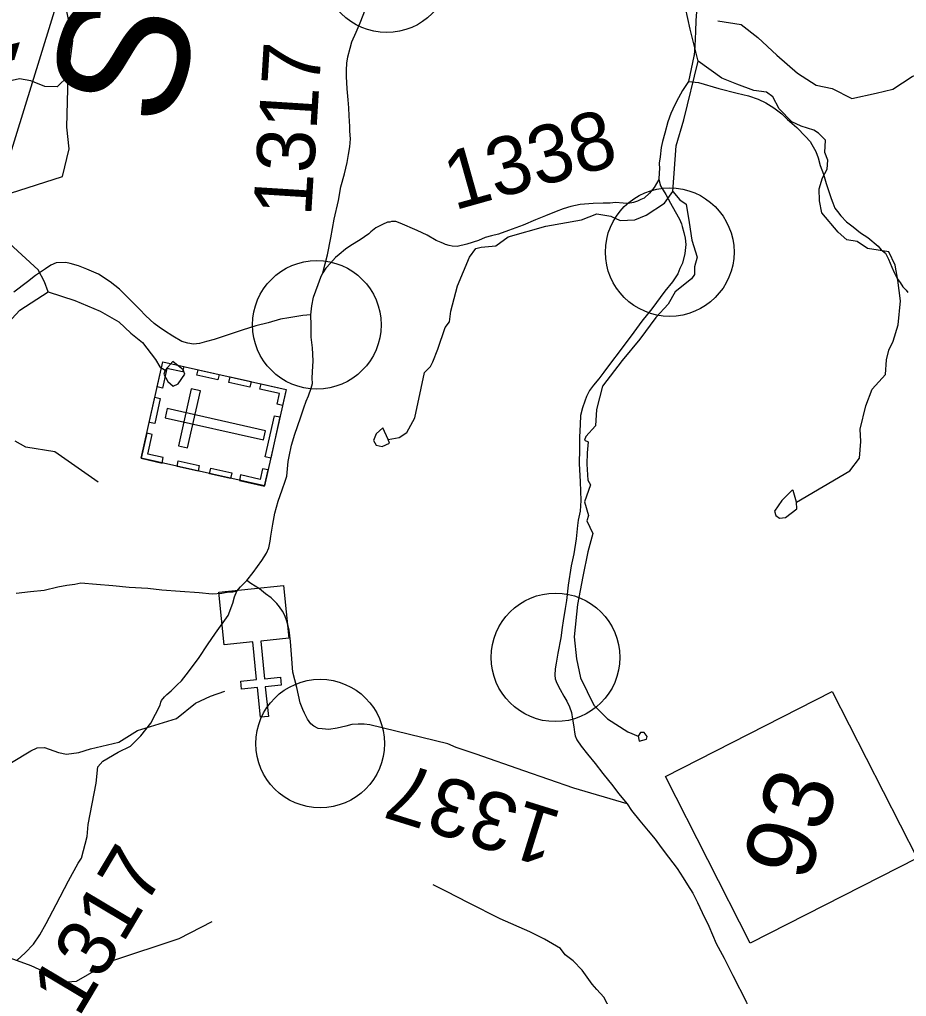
# Model space of a CAD drawing. Extents: x 1347947 to 1350662, y 1027710 to 1030532.
# Drawn here: x 1348130.6 to 1348199.3, y 1028802.3 to 1028877.9 of the extents above; entities that cross this region are included whole.
import ezdxf

# ---------------------------------------------------------------- set-up
doc = ezdxf.new("R2010")
doc.units = 0
for name, color, linetype in [('Default', 7, 'Continuous'), ('Prop Leader Line Light', 7, 'Continuous'), ('Prop Leader Line Medium', 7, 'Continuous'), ('Sheet Data Field CELL', 7, 'Continuous')]:
    doc.layers.add(name, color=color, linetype=linetype)

msp = doc.modelspace()

# ---------------------------------------------------------------- linework, layer by layer
at = {"layer": 'Default'}
for points in [[(1348181.173, 1028864.602), (1348181.411, 1028868.131), (1348182.007, 1028870.153), (1348183.114, 1028874.691), (1348182.5, 1028877.178), (1348181.789, 1028880.507), (1348181.554, 1028882.206), (1348180.125, 1028885.595), (1348177.668, 1028887.359), (1348177.766, 1028888.565), (1348175.539, 1028889.88), (1348174.087, 1028891.944), (1348172.247, 1028893.722), (1348171.975, 1028895.42), (1348169.288, 1028897.206), (1348170.716, 1028902.659), (1348170.544, 1028903.22), (1348170.926, 1028904.027), (1348172.25, 1028905.178)], [(1348129.882, 1028864.481), (1348133.892, 1028865.779), (1348134.416, 1028867.913), (1348134.237, 1028869.593), (1348134.337, 1028873.534), (1348134.702, 1028876.269), (1348134.116, 1028879.192)], [(1348154.052, 1028858.309), (1348154.429, 1028859.696), (1348154.674, 1028861.01), (1348154.928, 1028862.454), (1348155.26, 1028863.906), (1348155.463, 1028864.977), (1348155.732, 1028865.982), (1348155.95, 1028866.845), (1348156.051, 1028867.482), (1348156.148, 1028868.059), (1348156.2, 1028868.674), (1348156.153, 1028869.271), (1348156.138, 1028869.643), (1348156.089, 1028870.464), (1348156.063, 1028871.087), (1348156.011, 1028871.693), (1348155.938, 1028872.563), (1348155.889, 1028873.508), (1348155.9, 1028874.001), (1348155.925, 1028874.542), (1348155.988, 1028875.036), (1348156.175, 1028875.713), (1348156.31, 1028876.196), (1348156.63, 1028876.94), (1348156.962, 1028877.661), (1348157.372, 1028878.721)], [(1348183.002, 1028878.527), (1348182.95, 1028877.851), (1348182.921, 1028877.006), (1348182.87, 1028875.861), (1348182.807, 1028875.151), (1348182.795, 1028875.098), (1348182.367, 1028873.135)], [(1348184.639, 1028877.83), (1348186.451, 1028877.533), (1348187.738, 1028876.527), (1348189.205, 1028875.169), (1348190.805, 1028873.768), (1348192.268, 1028872.852), (1348193.506, 1028872.595), (1348195.013, 1028871.811), (1348196.908, 1028872.221), (1348198.186, 1028872.539), (1348199.68, 1028873.52), (1348200.869, 1028874.013), (1348202.273, 1028875.17), (1348203.631, 1028876.635), (1348204.863, 1028877.262)], [(1348190.741, 1028840.554), (1348194.856, 1028842.987), (1348195.618, 1028843.944), (1348195.705, 1028845.239), (1348195.677, 1028846.208), (1348196.106, 1028848.016), (1348196.6, 1028849.311), (1348197.627, 1028850.44), (1348197.718, 1028851.571), (1348197.882, 1028852.33), (1348198.226, 1028853.025), (1348198.604, 1028854.278), (1348198.791, 1028856.151), (1348198.595, 1028857.749), (1348198.387, 1028858.903), (1348197.874, 1028859.939), (1348196.227, 1028860.189), (1348195.438, 1028860.73), (1348194.624, 1028860.852), (1348193.957, 1028861.452), (1348192.707, 1028862.95), (1348192.527, 1028863.891), (1348192.486, 1028864.823), (1348192.737, 1028865.653), (1348193.118, 1028866.335), (1348193.159, 1028867.035), (1348192.936, 1028867.623), (1348192.988, 1028868.584), (1348192.441, 1028869.121), (1348192.073, 1028869.352), (1348191.098, 1028869.653), (1348190.367, 1028870.011), (1348189.389, 1028871.005), (1348188.898, 1028871.931), (1348188.417, 1028872.305), (1348187.445, 1028872.44), (1348186.118, 1028872.905), (1348184.957, 1028873.372), (1348183.114, 1028874.691)], [(1348134.337, 1028873.534), (1348133.478, 1028872.712), (1348132.529, 1028872.739), (1348131.459, 1028873.175), (1348130.578, 1028873.34), (1348129.534, 1028873.095), (1348127.961, 1028872.564), (1348126.044, 1028871.747), (1348124.621, 1028871.47), (1348123.627, 1028871.716), (1348122.614, 1028871.561), (1348121.066, 1028871.043), (1348120.401, 1028870.602), (1348119.825, 1028870.294), (1348119.077, 1028870.311), (1348117.324, 1028870.721), (1348115.354, 1028870.921), (1348113.144, 1028870.9), (1348111.773, 1028871.175), (1348110.074, 1028871.566), (1348108.503, 1028871.505), (1348106.599, 1028871.6)], [(1348182.367, 1028873.135), (1348181.921, 1028872.426), (1348181.608, 1028871.847), (1348181.325, 1028871.309), (1348181.005, 1028870.658), (1348180.763, 1028869.99), (1348180.532, 1028869.114), (1348180.371, 1028868.478), (1348180.265, 1028868.003), (1348180.175, 1028867.301), (1348180.103, 1028866.796), (1348180.129, 1028866.349), (1348180.113, 1028866.069), (1348180.088, 1028865.547)], [(1348182.367, 1028873.135), (1348183.153, 1028873.056), (1348184.723, 1028872.591), (1348186.131, 1028872.233), (1348187.023, 1028872.007), (1348187.776, 1028871.766), (1348188.362, 1028871.465), (1348188.993, 1028871.085), (1348189.61, 1028870.611), (1348190.031, 1028870.183), (1348190.754, 1028869.564), (1348191.426, 1028868.875), (1348191.793, 1028868.473), (1348191.913, 1028868.233), (1348192.222, 1028867.716), (1348192.417, 1028867.221), (1348192.574, 1028866.617), (1348192.837, 1028865.958), (1348193.039, 1028865.231), (1348193.228, 1028864.596), (1348193.409, 1028864.056), (1348193.548, 1028863.72), (1348193.711, 1028863.327), (1348193.902, 1028863.049), (1348194.179, 1028862.726), (1348194.611, 1028862.27), (1348195.128, 1028861.87), (1348195.689, 1028861.395), (1348196.256, 1028861.035), (1348197.064, 1028860.377), (1348197.298, 1028860.101), (1348197.639, 1028859.841), (1348197.864, 1028859.375), (1348198.129, 1028858.752), (1348198.309, 1028858.33), (1348198.534, 1028857.866), (1348198.751, 1028857.554), (1348198.972, 1028857.234), (1348199.224, 1028856.962), (1348199.36, 1028856.776)], [(1348180.088, 1028865.547), (1348179.708, 1028864.915), (1348179.349, 1028864.476), (1348178.935, 1028864.097), (1348178.679, 1028863.991), (1348178.428, 1028863.855), (1348178.103, 1028863.743), (1348177.694, 1028863.683), (1348177.311, 1028863.692), (1348176.722, 1028863.756), (1348176.32, 1028863.712), (1348175.772, 1028863.708), (1348174.986, 1028863.686), (1348173.975, 1028863.59), (1348173.254, 1028863.454), (1348172.662, 1028863.272), (1348172.135, 1028863.049), (1348171.291, 1028862.73), (1348170.532, 1028862.424), (1348169.57, 1028862.005), (1348168.446, 1028861.581), (1348167.657, 1028861.305), (1348167.119, 1028861.166), (1348166.625, 1028861.032), (1348166.107, 1028860.806), (1348165.201, 1028860.52), (1348164.451, 1028860.357), (1348164.062, 1028860.36), (1348163.844, 1028860.431), (1348163.57, 1028860.513), (1348163.411, 1028860.587), (1348163.224, 1028860.666), (1348162.844, 1028860.823), (1348162.15, 1028861.215), (1348161.356, 1028861.581), (1348160.04, 1028862.15), (1348159.716, 1028862.276), (1348159.598, 1028862.294), (1348159.376, 1028862.275), (1348159.244, 1028862.243), (1348159.073, 1028862.221), (1348158.69, 1028862.053), (1348158.17, 1028861.786), (1348157.789, 1028861.481), (1348157.63, 1028861.326), (1348156.939, 1028860.853), (1348156.222, 1028860.431), (1348155.813, 1028860.136), (1348155.321, 1028859.716), (1348155.044, 1028859.496), (1348154.644, 1028859.065), (1348154.287, 1028858.68), (1348154.052, 1028858.309)], [(1348180.088, 1028865.547), (1348180.208, 1028865.048), (1348180.619, 1028864.367), (1348180.975, 1028863.692), (1348181.345, 1028863.063), (1348181.684, 1028862.472), (1348181.829, 1028862.112), (1348181.892, 1028861.901), (1348182.02, 1028861.441), (1348182.123, 1028860.993), (1348182.156, 1028860.509), (1348182.089, 1028859.793), (1348181.912, 1028859.045), (1348181.829, 1028858.89), (1348181.715, 1028858.645), (1348181.541, 1028858.237), (1348181.124, 1028857.618), (1348180.543, 1028856.878), (1348179.546, 1028855.525), (1348178.76, 1028854.555), (1348178.137, 1028853.72), (1348177.149, 1028852.39), (1348176.257, 1028851.213), (1348175.805, 1028850.617), (1348175.424, 1028850.111), (1348175.022, 1028849.599), (1348174.717, 1028849.196), (1348174.475, 1028848.731), (1348174.338, 1028848.369), (1348174.167, 1028847.844), (1348174.009, 1028847.256), (1348173.996, 1028846.555), (1348173.928, 1028845.585), (1348173.935, 1028844.665), (1348173.918, 1028843.538), (1348173.974, 1028842.113), (1348174.032, 1028840.677), (1348173.983, 1028839.864), (1348173.843, 1028839.154), (1348173.784, 1028838.742), (1348173.671, 1028837.715), (1348173.485, 1028836.538), (1348173.299, 1028835.623), (1348173.062, 1028834.111), (1348172.919, 1028832.938), (1348172.823, 1028832.326), (1348172.669, 1028831.36), (1348172.592, 1028830.85), (1348172.485, 1028830.038), (1348172.267, 1028828.857), (1348172.12, 1028828.075), (1348172.058, 1028827.63), (1348172.019, 1028827.159), (1348172.039, 1028826.866), (1348172.17, 1028826.535), (1348172.425, 1028826.04), (1348172.716, 1028825.531), (1348172.959, 1028825.147), (1348173.166, 1028824.689), (1348173.322, 1028824.274), (1348173.395, 1028823.735), (1348173.494, 1028823.147), (1348173.539, 1028822.751), (1348173.596, 1028822.467), (1348173.718, 1028822.145), (1348174.053, 1028821.642), (1348174.544, 1028821.046), (1348175.153, 1028820.318), (1348175.739, 1028819.543), (1348176.502, 1028818.587), (1348176.945, 1028817.985), (1348177.63, 1028817.196)], [(1348159.116, 1028845.404), (1348159.983, 1028845.549), (1348160.567, 1028845.936), (1348161.194, 1028847.084), (1348161.666, 1028849.365), (1348161.927, 1028850.579), (1348162.404, 1028851.065), (1348162.585, 1028851.409), (1348162.971, 1028852.396), (1348163.52, 1028854.08), (1348163.88, 1028854.524), (1348163.965, 1028855.352), (1348164.488, 1028857.31), (1348165.428, 1028859.53), (1348165.9, 1028860.18), (1348166.31, 1028860.302), (1348167.468, 1028860.406), (1348168.422, 1028861.092), (1348171.321, 1028861.914), (1348174.084, 1028862.413), (1348175.285, 1028862.87), (1348176.348, 1028862.702), (1348177.085, 1028862.362), (1348178.206, 1028862.419), (1348179.106, 1028862.777), (1348180.515, 1028863.712), (1348181.173, 1028864.602)], [(1348181.173, 1028864.602), (1348181.707, 1028863.967), (1348182.188, 1028863.633), (1348182.429, 1028862.199), (1348182.634, 1028860.835), (1348183.034, 1028859.525), (1348182.844, 1028858.762), (1348182.831, 1028858.177), (1348182.603, 1028857.838), (1348181.333, 1028856.837), (1348180.79, 1028855.893), (1348179.857, 1028854.841), (1348178.609, 1028853.183), (1348177.238, 1028851.507), (1348175.709, 1028849.529), (1348175.243, 1028847.735), (1348175.181, 1028846.458), (1348174.415, 1028845.646), (1348174.32, 1028845.353), (1348174.604, 1028845.231), (1348174.531, 1028844.37), (1348174.51, 1028843.493), (1348174.581, 1028842.261), (1348174.788, 1028841.899), (1348174.327, 1028840.575), (1348174.628, 1028839.504), (1348174.498, 1028839.104), (1348174.975, 1028838.124), (1348174.568, 1028836.694), (1348174.183, 1028834.785), (1348173.773, 1028832.619), (1348173.513, 1028830.125), (1348173.694, 1028828.415), (1348174.015, 1028826.954), (1348175.037, 1028824.822)], [(1348129.086, 1028853.773), (1348130.603, 1028855.413), (1348132.797, 1028856.841), (1348132.513, 1028857.608), (1348132.005, 1028858.541), (1348129.808, 1028860.58)], [(1348153.137, 1028855.064), (1348152.502, 1028855.001), (1348151.433, 1028854.824), (1348150.786, 1028854.723), (1348149.833, 1028854.447), (1348148.865, 1028854.209), (1348147.807, 1028853.863), (1348146.407, 1028853.413), (1348145.643, 1028853.149), (1348145.058, 1028852.981), (1348144.52, 1028852.829), (1348144.057, 1028852.787), (1348143.619, 1028852.866), (1348143.148, 1028852.997), (1348142.447, 1028853.413), (1348141.798, 1028853.814), (1348141.388, 1028854.098), (1348141.002, 1028854.397), (1348140.352, 1028854.989), (1348139.854, 1028855.49), (1348139.012, 1028856.353), (1348138.315, 1028857.043), (1348137.599, 1028857.618), (1348136.681, 1028858.214), (1348135.78, 1028858.599), (1348135.132, 1028858.843), (1348134.494, 1028859.042), (1348134.152, 1028859.112), (1348133.419, 1028859.071), (1348133.01, 1028858.889), (1348132.576, 1028858.605), (1348131.819, 1028858.113), (1348131.186, 1028857.622), (1348130.144, 1028856.816)], [(1348153.137, 1028855.064), (1348153.217, 1028855.743), (1348153.343, 1028856.42), (1348153.51, 1028856.925), (1348153.704, 1028857.408), (1348153.904, 1028857.983), (1348154.052, 1028858.309)], [(1348132.797, 1028856.841), (1348134.868, 1028856.177), (1348136.815, 1028855.332), (1348138.264, 1028854.519), (1348139.183, 1028853.647), (1348140.085, 1028852.903), (1348141.112, 1028851.585), (1348141.426, 1028851.026), (1348141.849, 1028850.777)], [(1348148.176, 1028834.476), (1348148.656, 1028835.108), (1348149.333, 1028836.041), (1348149.698, 1028836.602), (1348149.869, 1028837.005), (1348149.939, 1028837.266), (1348149.991, 1028837.533), (1348150.028, 1028837.928), (1348150.121, 1028838.372), (1348150.182, 1028838.839), (1348150.354, 1028839.689), (1348150.598, 1028840.623), (1348150.907, 1028841.515), (1348151.135, 1028842.168), (1348151.269, 1028842.55), (1348151.309, 1028842.842), (1348151.381, 1028843.687), (1348151.44, 1028844.093), (1348151.621, 1028844.954), (1348151.882, 1028845.806), (1348152.332, 1028847.082), (1348152.583, 1028847.86), (1348152.767, 1028848.372), (1348152.946, 1028848.795), (1348153.166, 1028849.371), (1348153.249, 1028849.726), (1348153.243, 1028850.159), (1348153.267, 1028850.638), (1348153.304, 1028851.5), (1348153.272, 1028852.498), (1348153.163, 1028853.324), (1348153.15, 1028854.263), (1348153.137, 1028855.064)], [(1348141.849, 1028850.777), (1348141.74, 1028850.468), (1348142.048, 1028849.891), (1348142.475, 1028849.537), (1348142.861, 1028849.709), (1348143.365, 1028850.45), (1348143.243, 1028850.798), (1348142.449, 1028851.443), (1348141.849, 1028850.777)], [(1348159.116, 1028845.404), (1348158.716, 1028846.3), (1348158.185, 1028845.833), (1348157.972, 1028845.336), (1348158.185, 1028844.955), (1348158.658, 1028844.85), (1348159.217, 1028845.105), (1348159.116, 1028845.404)], [(1348136.675, 1028842.087), (1348133.32, 1028844.454), (1348131.071, 1028844.812), (1348130.229, 1028845.278)], [(1348190.741, 1028840.554), (1348190.487, 1028841.459), (1348190.395, 1028841.49), (1348189.598, 1028840.668), (1348189.044, 1028839.842), (1348189.13, 1028839.506), (1348189.425, 1028839.3), (1348189.895, 1028839.361), (1348190.764, 1028840.035), (1348190.741, 1028840.554)], [(1348147.389, 1028833.662), (1348147.095, 1028833.575), (1348146.778, 1028833.571), (1348146.227, 1028833.484), (1348145.482, 1028833.437), (1348144.478, 1028833.515), (1348143.006, 1028833.642), (1348141.594, 1028833.746), (1348140.519, 1028833.866), (1348139.076, 1028833.943), (1348137.803, 1028834.059), (1348136.524, 1028834.185), (1348135.334, 1028834.274), (1348134.853, 1028834.176), (1348134.24, 1028834.101), (1348133.546, 1028833.961), (1348132.483, 1028833.719), (1348131.423, 1028833.599), (1348130.319, 1028833.473)], [(1348147.389, 1028833.662), (1348147.681, 1028833.985), (1348147.811, 1028834.124), (1348148.176, 1028834.476)], [(1348177.63, 1028817.196), (1348173.483, 1028818.396), (1348169.623, 1028819.744), (1348165.922, 1028821.041), (1348164.381, 1028821.559), (1348163.736, 1028821.844), (1348157.69, 1028823.306), (1348157.261, 1028823.363), (1348156.784, 1028823.352), (1348156.313, 1028823.331), (1348155.847, 1028823.211), (1348155.182, 1028823.056), (1348154.532, 1028822.957), (1348154.007, 1028823.003), (1348153.688, 1028823.016), (1348153.355, 1028823.215), (1348153.127, 1028823.381), (1348152.86, 1028823.733), (1348152.646, 1028824.201), (1348152.522, 1028824.489), (1348152.317, 1028825.022), (1348152.046, 1028826.205), (1348151.726, 1028827.388), (1348151.629, 1028828.747), (1348151.552, 1028829.759), (1348151.448, 1028830.637), (1348151.265, 1028831.322), (1348151.124, 1028831.777), (1348150.932, 1028832.11), (1348150.698, 1028832.435), (1348150.488, 1028832.697), (1348150.068, 1028833.129), (1348149.633, 1028833.445), (1348149.157, 1028833.834), (1348148.825, 1028834.049), (1348148.477, 1028834.254), (1348148.176, 1028834.476)], [(1348130.404, 1028805.091), (1348131.021, 1028805.662), (1348131.655, 1028806.31), (1348132.154, 1028807.052), (1348132.648, 1028807.934), (1348133.406, 1028809.405), (1348134.363, 1028811.237), (1348135.114, 1028812.601), (1348135.383, 1028812.978), (1348135.824, 1028814.658), (1348135.884, 1028815.578), (1348136.515, 1028818.791), (1348136.639, 1028820.045), (1348137.026, 1028820.502), (1348138.22, 1028821.198), (1348139.172, 1028821.652), (1348139.964, 1028822.456), (1348140.737, 1028823.448), (1348141.454, 1028824.839), (1348141.511, 1028825.063), (1348141.577, 1028825.191), (1348141.8, 1028825.467), (1348141.988, 1028825.663), (1348142.311, 1028825.94), (1348142.591, 1028826.22), (1348142.793, 1028826.394), (1348143.106, 1028826.726), (1348143.67, 1028827.414), (1348144.481, 1028828.527), (1348145.122, 1028829.505), (1348145.76, 1028830.399), (1348146.728, 1028831.761), (1348147.081, 1028832.737), (1348147.208, 1028833.223), (1348147.389, 1028833.662)], [(1348136.07, 1028821.454), (1348138.269, 1028821.97), (1348139.701, 1028822.855), (1348142.722, 1028823.795), (1348144.195, 1028824.973), (1348145.366, 1028825.522), (1348146.479, 1028825.906)], [(1348175.037, 1028824.822), (1348176.099, 1028823.776), (1348177.679, 1028822.755), (1348178.483, 1028822.432)], [(1348178.483, 1028822.432), (1348178.55, 1028822.041), (1348179.119, 1028822.209), (1348179.182, 1028822.391), (1348178.95, 1028822.718), (1348178.646, 1028822.722), (1348178.483, 1028822.432)], [(1348129.231, 1028819.878), (1348129.958, 1028820.378), (1348131.439, 1028821.285), (1348131.93, 1028821.52), (1348132.515, 1028821.56), (1348133.595, 1028821.16), (1348134.224, 1028821.042), (1348135.173, 1028821.157), (1348136.07, 1028821.454)], [(1348177.63, 1028817.196), (1348177.951, 1028816.679), (1348178.604, 1028815.86), (1348179.239, 1028815.109), (1348179.785, 1028814.451), (1348180.251, 1028813.799), (1348180.826, 1028813.049), (1348181.502, 1028812.182), (1348181.961, 1028811.452), (1348182.308, 1028810.923), (1348182.713, 1028810.274), (1348183.069, 1028809.538), (1348183.436, 1028808.777), (1348183.946, 1028807.722), (1348184.527, 1028806.371), (1348185.137, 1028805.231), (1348185.814, 1028803.903), (1348186.876, 1028801.84), (1348187.025, 1028801.214), (1348186.961, 1028800.418), (1348186.847, 1028799.991), (1348186.821, 1028799.833)], [(1348176.029, 1028797.668), (1348176.808, 1028799.376), (1348176.614, 1028800.692), (1348175.809, 1028802.229), (1348175.269, 1028802.809), (1348174.914, 1028803.228), (1348174.138, 1028804.31), (1348173.439, 1028805.024), (1348172.827, 1028805.506), (1348172.457, 1028805.989), (1348171.235, 1028806.712), (1348170.086, 1028807.288), (1348167.778, 1028808.283), (1348165.346, 1028809.52), (1348163.641, 1028810.394), (1348162.603, 1028810.922)], [(1348145.463, 1028808.058), (1348142.902, 1028806.747), (1348137.685, 1028805.016), (1348134.951, 1028803.424), (1348133.951, 1028803.344), (1348132.763, 1028804.055), (1348131.47, 1028804.635), (1348127.629, 1028806.048)]]:
    msp.add_lwpolyline(points, dxfattribs=at)
for points in [[(1348139.987, 1028843.944), (1348141.662, 1028851.418), (1348151.221, 1028849.276), (1348149.547, 1028841.802)], [(1348143.29, 1028851.056), (1348143.195, 1028850.63), (1348141.986, 1028850.901), (1348141.645, 1028849.378), (1348141.227, 1028849.472), (1348141.664, 1028851.42)], [(1348145.938, 1028850.013), (1348144.312, 1028850.377), (1348144.408, 1028850.805), (1348146.034, 1028850.441)], [(1348148.413, 1028849.458), (1348146.787, 1028849.822), (1348146.882, 1028850.249), (1348148.508, 1028849.885)], [(1348142.885, 1028844.904), (1348143.587, 1028844.746), (1348144.577, 1028849.167), (1348143.876, 1028849.324)], [(1348150.943, 1028848.033), (1348150.512, 1028848.129), (1348150.697, 1028848.955), (1348149.179, 1028849.295), (1348149.273, 1028849.713), (1348151.221, 1028849.276)], [(1348140.611, 1028846.724), (1348141.047, 1028848.67), (1348141.475, 1028848.574), (1348141.039, 1028846.629)], [(1348142.004, 1028847.79), (1348141.847, 1028847.089), (1348149.46, 1028845.384), (1348149.618, 1028846.085)], [(1348149.599, 1028844.056), (1348150.313, 1028847.242), (1348150.741, 1028847.146), (1348150.027, 1028843.96)], [(1348141.613, 1028843.579), (1348141.709, 1028844.005), (1348140.5, 1028844.276), (1348140.842, 1028845.799), (1348140.424, 1028845.893), (1348139.987, 1028843.944)], [(1348144.397, 1028842.955), (1348142.771, 1028843.319), (1348142.867, 1028843.747), (1348144.493, 1028843.382)], [(1348146.921, 1028842.389), (1348145.295, 1028842.753), (1348145.39, 1028843.181), (1348147.016, 1028842.816)], [(1348149.823, 1028843.044), (1348149.392, 1028843.141), (1348149.207, 1028842.315), (1348147.69, 1028842.655), (1348147.596, 1028842.237), (1348149.545, 1028841.8)], [(1348151.425, 1028830.012), (1348149.247, 1028829.785), (1348149.545, 1028826.87), (1348150.77, 1028826.995), (1348150.832, 1028826.384), (1348149.607, 1028826.259), (1348149.843, 1028823.957), (1348149.229, 1028823.894), (1348148.994, 1028826.196), (1348147.769, 1028826.071), (1348147.707, 1028826.682), (1348148.931, 1028826.808), (1348148.633, 1028829.722), (1348146.426, 1028829.5), (1348146.01, 1028833.575), (1348151.009, 1028834.086)], [(1348187.153, 1028806.398), (1348180.58, 1028819.317), (1348193.499, 1028825.89), (1348200.072, 1028812.971)]]:
    msp.add_lwpolyline(points, close=True, dxfattribs=at)
at = {"layer": 'Prop Leader Line Light'}
for centre in [(1348159.005, 1028881.9), (1348159.005, 1028881.9), (1348180.919, 1028859.915), (1348180.919, 1028859.915), (1348153.597, 1028854.282), (1348153.597, 1028854.282), (1348172.074, 1028828.531), (1348172.074, 1028828.531), (1348153.855, 1028821.853), (1348153.855, 1028821.853)]:
    msp.add_circle(centre, 4.978, dxfattribs=at)
at = {"layer": 'Prop Leader Line Medium'}
msp.add_line((1348144.086, 1028913.426), (1348126.436, 1028856.535), dxfattribs=at)

# ---------------------------------------------------------------- texts
at = {"layer": 'Default'}
msp.add_text('93', height=5.3865, rotation=71.96667, dxfattribs=at).set_placement((1348191.562, 1028811.02))
at = {"layer": 'Prop Leader Line Light'}
for s, rotation, p in [('1317', 86.42073, (1348153.148, 1028862.627)), ('1338', 15.68856, (1348164.225, 1028863.132)), ('1337', 162.73096, (1348172.738, 1028816.507)), ('1317', 59.19849, (1348135.143, 1028800.566))]:
    msp.add_text(s, height=4.5, rotation=rotation, dxfattribs=at).set_placement(p)
at = {"layer": 'Sheet Data Field CELL'}
for s, p in [('PROJECT', (1348125.315, 1028859.012)), ('SITE', (1348142.078, 1028869.237))]:
    msp.add_text(s, height=10, rotation=72.88342, dxfattribs=at).set_placement(p)

doc.saveas('drawing.dxf')
